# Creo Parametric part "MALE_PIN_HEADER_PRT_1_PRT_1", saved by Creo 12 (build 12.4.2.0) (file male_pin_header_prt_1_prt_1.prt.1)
Units: Custom; MM, KILOGRAM, SECS

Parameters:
  PTC_WM_ITERATION = "0"
  PTC_WM_VERSION = "-.0"
  PTC_WM_LIFECYCLE_STATE = "In Work"
  PTC_WM_LIFECYCLE = "MO_CADDocument"
  PTC_WM_CREATED_BY = "Maximilian Roepper (Z0017RMS: MO)"
  PTC_WM_CREATED_ON = "18-Sep-26 11:36:42 AM"
  PTC_WM_MODIFIED_BY = "Maximilian Roepper (Z0017RMS: MO)"
  PTC_WM_MODIFIED_ON = "18-Sep-26 11:36:46 AM"
  PDMLINKNUMBER = "PDM000071455200"
  PTC_WM_NAME = "male_pin_header_prt_1_prt_1.prt"
  PTC_WM_NUMBER = "PDM000071455200"

Other parameters: WEIGHT, WEIGHT_FACTOR, WEIGHT_ADD, _MASS_TEMP, _DIFF_TEMP, MC_ERRORS, SUPPLIER

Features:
  1. coordinate system
  2. datum plane "PRT_YZ"
  3. datum plane "PRT_XY"
  4. datum plane "PRT_XZ"
  5. coordinate system
  6. datum axis
  7. datum axis
  8. datum axis
  9. coordinate system
  10. imported feature
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
Other named items: PRT, SIEMENS_MO, DRW_VIEW_ORG, PRT_X, PRT_Y, PRT_Z, CS0, ROUGH_GROB

Layers: 00_STD_CSYS-KSYS, 01_STD_PLANES-EBENEN, 02_STD_AXES-ACHSEN, 03_STD_CSYS-KSYS, 24_IMPORT_FEAT-IMPORT_KE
